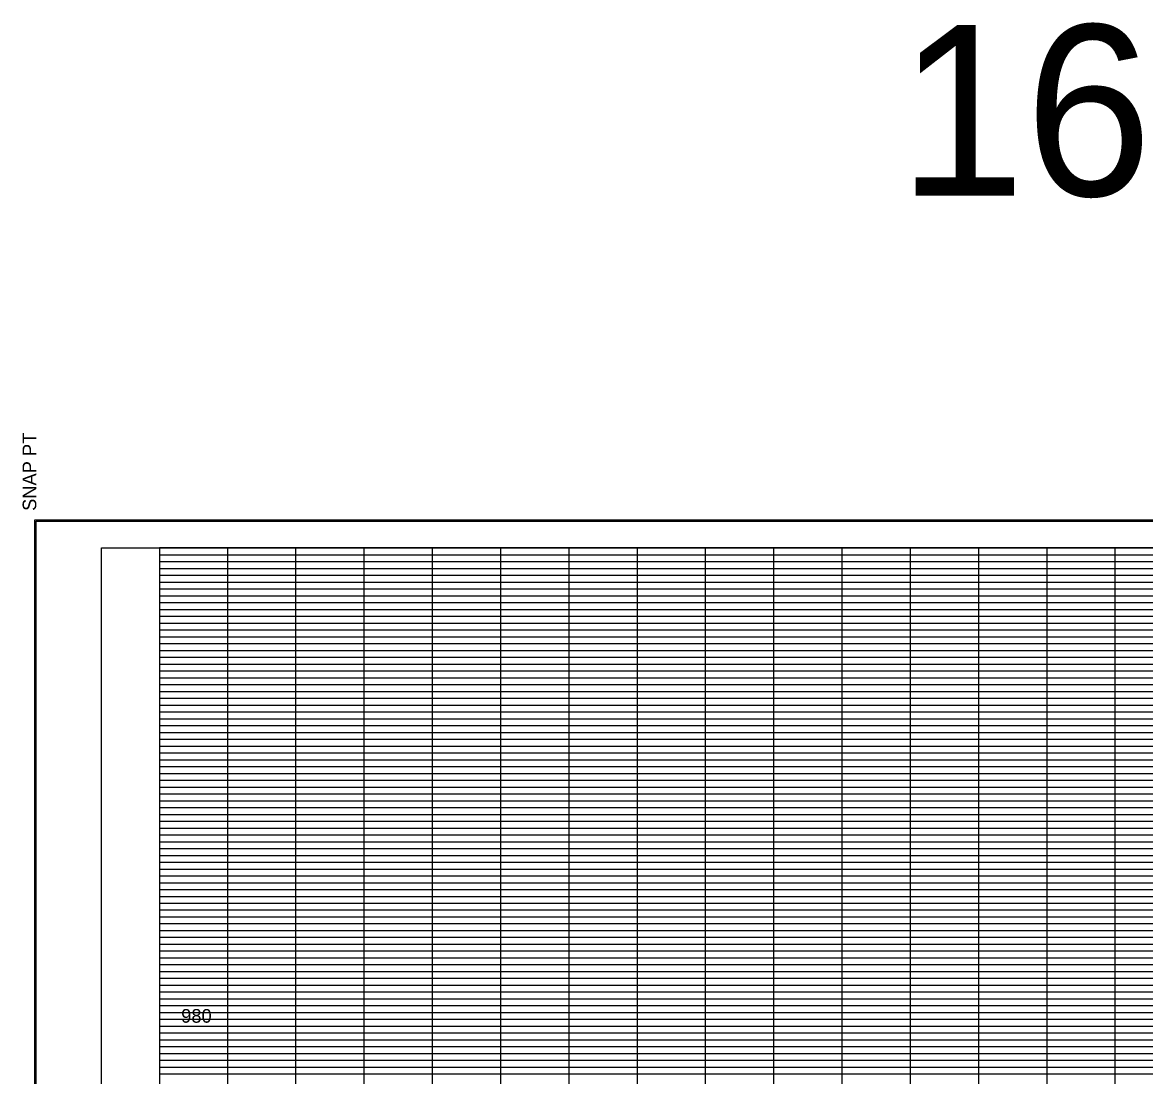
# Model space of a CAD drawing. Extents: x 2313580 to 2322968, y 282099 to 303247.
# Drawn here: x 2320006 to 2320334.7, y 287853.2 to 288161.5 of the extents above; entities that cross this region are included whole.
import ezdxf

# ---------------------------------------------------------------- set-up
doc = ezdxf.new("R2010")
doc.units = 0
for name, color, linetype in [('DESIGN - SCRATCH - User 1', 7, 'Continuous'), ('DESIGN - SHEET - Corner Text', 7, 'Continuous'), ('DESIGN - SHEET - Light Grid', 7, 'Continuous'), ('DESIGN - SHEET - Linework', 7, 'Continuous'), ('DESIGN - SHEET - Plot Shape', 7, 'Continuous'), ('DESIGN - TYPICAL - Text', 7, 'Continuous')]:
    doc.layers.add(name, color=color, linetype=linetype)

msp = doc.modelspace()

# ---------------------------------------------------------------- linework, layer by layer
at = {"layer": 'DESIGN - SHEET - Light Grid'}
for p, q in [((2320046.08, 288005.67), (2320206.08, 288005.67)), ((2320046.08, 288003.67), (2320206.08, 288003.67)), ((2320206.08, 288005.67), (2320366.08, 288005.67)), ((2320206.08, 288003.67), (2320366.08, 288003.67)), ((2320046.08, 288001.67), (2320206.08, 288001.67)), ((2320206.08, 288001.67), (2320366.08, 288001.67)), ((2320046.08, 287999.67), (2320206.08, 287999.67)), ((2320046.08, 287997.67), (2320206.08, 287997.67)), ((2320206.08, 287999.67), (2320366.08, 287999.67)), ((2320206.08, 287997.67), (2320366.08, 287997.67)), ((2320046.08, 287995.67), (2320206.08, 287995.67)), ((2320046.08, 287993.67), (2320206.08, 287993.67)), ((2320206.08, 287995.67), (2320366.08, 287995.67)), ((2320206.08, 287993.67), (2320366.08, 287993.67)), ((2320046.08, 287991.67), (2320206.08, 287991.67)), ((2320206.08, 287991.67), (2320366.08, 287991.67)), ((2320046.08, 287989.67), (2320206.08, 287989.67)), ((2320206.08, 287989.67), (2320366.08, 287989.67)), ((2320046.08, 287985.67), (2320206.08, 287985.67)), ((2320046.08, 287983.67), (2320206.08, 287983.67)), ((2320206.08, 287985.67), (2320366.08, 287985.67)), ((2320206.08, 287983.67), (2320366.08, 287983.67)), ((2320046.08, 287981.67), (2320206.08, 287981.67)), ((2320206.08, 287981.67), (2320366.08, 287981.67)), ((2320046.08, 287979.67), (2320206.08, 287979.67)), ((2320046.08, 287977.67), (2320206.08, 287977.67)), ((2320206.08, 287979.67), (2320366.08, 287979.67)), ((2320206.08, 287977.67), (2320366.08, 287977.67)), ((2320046.08, 287975.67), (2320206.08, 287975.67)), ((2320046.08, 287973.67), (2320206.08, 287973.67)), ((2320206.08, 287975.67), (2320366.08, 287975.67)), ((2320206.08, 287973.67), (2320366.08, 287973.67)), ((2320046.08, 287971.67), (2320206.08, 287971.67)), ((2320206.08, 287971.67), (2320366.08, 287971.67)), ((2320046.08, 287969.67), (2320206.08, 287969.67)), ((2320206.08, 287969.67), (2320366.08, 287969.67)), ((2320046.08, 287965.67), (2320206.08, 287965.67)), ((2320046.08, 287963.67), (2320206.08, 287963.67)), ((2320206.08, 287965.67), (2320366.08, 287965.67)), ((2320206.08, 287963.67), (2320366.08, 287963.67)), ((2320046.08, 287961.67), (2320206.08, 287961.67)), ((2320206.08, 287961.67), (2320366.08, 287961.67)), ((2320046.08, 287959.67), (2320206.08, 287959.67)), ((2320046.08, 287957.67), (2320206.08, 287957.67)), ((2320206.08, 287959.67), (2320366.08, 287959.67)), ((2320206.08, 287957.67), (2320366.08, 287957.67)), ((2320046.08, 287955.67), (2320206.08, 287955.67)), ((2320206.08, 287955.67), (2320366.08, 287955.67)), ((2320046.08, 287953.67), (2320206.08, 287953.67)), ((2320046.08, 287951.67), (2320206.08, 287951.67)), ((2320206.08, 287953.67), (2320366.08, 287953.67)), ((2320206.08, 287951.67), (2320366.08, 287951.67)), ((2320046.08, 287949.67), (2320206.08, 287949.67)), ((2320206.08, 287949.67), (2320366.08, 287949.67)), ((2320046.08, 287945.67), (2320206.08, 287945.67)), ((2320206.08, 287945.67), (2320366.08, 287945.67)), ((2320046.08, 287943.67), (2320206.08, 287943.67)), ((2320046.08, 287941.67), (2320206.08, 287941.67)), ((2320206.08, 287943.67), (2320366.08, 287943.67)), ((2320206.08, 287941.67), (2320366.08, 287941.67)), ((2320046.08, 287939.67), (2320206.08, 287939.67)), ((2320046.08, 287937.67), (2320206.08, 287937.67)), ((2320206.08, 287939.67), (2320366.08, 287939.67)), ((2320206.08, 287937.67), (2320366.08, 287937.67)), ((2320046.08, 287935.67), (2320206.08, 287935.67)), ((2320206.08, 287935.67), (2320366.08, 287935.67)), ((2320046.08, 287933.67), (2320206.08, 287933.67)), ((2320046.08, 287931.67), (2320206.08, 287931.67)), ((2320206.08, 287933.67), (2320366.08, 287933.67)), ((2320206.08, 287931.67), (2320366.08, 287931.67)), ((2320046.08, 287929.67), (2320206.08, 287929.67)), ((2320206.08, 287929.67), (2320366.08, 287929.67)), ((2320046.08, 287925.67), (2320206.08, 287925.67)), ((2320206.08, 287925.67), (2320366.08, 287925.67)), ((2320046.08, 287923.67), (2320206.08, 287923.67)), ((2320046.08, 287921.67), (2320206.08, 287921.67)), ((2320206.08, 287923.67), (2320366.08, 287923.67)), ((2320206.08, 287921.67), (2320366.08, 287921.67)), ((2320046.08, 287919.67), (2320206.08, 287919.67)), ((2320046.08, 287917.67), (2320206.08, 287917.67)), ((2320206.08, 287919.67), (2320366.08, 287919.67)), ((2320206.08, 287917.67), (2320366.08, 287917.67)), ((2320046.08, 287915.67), (2320206.08, 287915.67)), ((2320206.08, 287915.67), (2320366.08, 287915.67)), ((2320046.08, 287913.67), (2320206.08, 287913.67)), ((2320046.08, 287911.67), (2320206.08, 287911.67)), ((2320206.08, 287913.67), (2320366.08, 287913.67)), ((2320206.08, 287911.67), (2320366.08, 287911.67)), ((2320046.08, 287909.67), (2320206.08, 287909.67)), ((2320206.08, 287909.67), (2320366.08, 287909.67)), ((2320046.08, 287905.67), (2320206.08, 287905.67)), ((2320206.08, 287905.67), (2320366.08, 287905.67)), ((2320046.08, 287903.67), (2320206.08, 287903.67)), ((2320046.08, 287901.67), (2320206.08, 287901.67)), ((2320206.08, 287903.67), (2320366.08, 287903.67)), ((2320206.08, 287901.67), (2320366.08, 287901.67)), ((2320046.08, 287899.67), (2320206.08, 287899.67)), ((2320206.08, 287899.67), (2320366.08, 287899.67)), ((2320046.08, 287897.67), (2320206.08, 287897.67)), ((2320046.08, 287895.67), (2320206.08, 287895.67)), ((2320206.08, 287897.67), (2320366.08, 287897.67)), ((2320206.08, 287895.67), (2320366.08, 287895.67)), ((2320046.08, 287893.67), (2320206.08, 287893.67)), ((2320046.08, 287891.67), (2320206.08, 287891.67)), ((2320206.08, 287893.67), (2320366.08, 287893.67)), ((2320206.08, 287891.67), (2320366.08, 287891.67)), ((2320046.08, 287889.67), (2320206.08, 287889.67)), ((2320206.08, 287889.67), (2320366.08, 287889.67)), ((2320046.08, 287885.67), (2320206.08, 287885.67)), ((2320206.08, 287885.67), (2320366.08, 287885.67)), ((2320046.08, 287883.67), (2320206.08, 287883.67)), ((2320046.08, 287881.67), (2320206.08, 287881.67)), ((2320206.08, 287883.67), (2320366.08, 287883.67)), ((2320206.08, 287881.67), (2320366.08, 287881.67)), ((2320046.08, 287879.67), (2320206.08, 287879.67)), ((2320206.08, 287879.67), (2320366.08, 287879.67)), ((2320046.08, 287877.67), (2320206.08, 287877.67)), ((2320046.08, 287875.67), (2320206.08, 287875.67)), ((2320206.08, 287877.67), (2320366.08, 287877.67)), ((2320206.08, 287875.67), (2320366.08, 287875.67)), ((2320046.08, 287873.67), (2320206.08, 287873.67)), ((2320046.08, 287871.67), (2320206.08, 287871.67)), ((2320206.08, 287873.67), (2320366.08, 287873.67)), ((2320206.08, 287871.67), (2320366.08, 287871.67)), ((2320046.08, 287869.67), (2320206.08, 287869.67)), ((2320206.08, 287869.67), (2320366.08, 287869.67)), ((2320046.08, 287865.67), (2320206.08, 287865.67)), ((2320206.08, 287865.67), (2320366.08, 287865.67)), ((2320046.08, 287863.67), (2320206.08, 287863.67)), ((2320206.08, 287863.67), (2320366.08, 287863.67)), ((2320046.08, 287861.67), (2320206.08, 287861.67)), ((2320046.08, 287859.67), (2320206.08, 287859.67)), ((2320206.08, 287861.67), (2320366.08, 287861.67)), ((2320206.08, 287859.67), (2320366.08, 287859.67)), ((2320046.08, 287857.67), (2320206.08, 287857.67)), ((2320046.08, 287855.67), (2320206.08, 287855.67)), ((2320206.08, 287857.67), (2320366.08, 287857.67)), ((2320206.08, 287855.67), (2320366.08, 287855.67)), ((2320046.08, 287853.67), (2320206.08, 287853.67)), ((2320206.08, 287853.67), (2320366.08, 287853.67))]:
    msp.add_line(p, q, dxfattribs=at)
at = {"layer": 'DESIGN - SHEET - Linework'}
for p, q in [((2320009.62, 287579.39), (2320009.62, 288015.95)), ((2320009.62, 288015.95), (2320690.42, 288015.95)), ((2320066.08, 287587.67), (2320066.08, 288007.67)), ((2320086.08, 287587.67), (2320086.08, 288007.67)), ((2320106.08, 287587.67), (2320106.08, 288007.67)), ((2320126.08, 287587.67), (2320126.08, 288007.67)), ((2320146.08, 287587.67), (2320146.08, 288007.67)), ((2320166.08, 287587.67), (2320166.08, 288007.67)), ((2320186.08, 287587.67), (2320186.08, 288007.67)), ((2320206.08, 287587.67), (2320206.08, 288007.67)), ((2320226.08, 287587.67), (2320226.08, 288007.67)), ((2320246.08, 287587.67), (2320246.08, 288007.67)), ((2320266.08, 287587.67), (2320266.08, 288007.67)), ((2320286.08, 287587.67), (2320286.08, 288007.67)), ((2320306.08, 287587.67), (2320306.08, 288007.67)), ((2320326.08, 287587.67), (2320326.08, 288007.67)), ((2320046.08, 287987.67), (2320606.08, 287987.67)), ((2320046.08, 287967.67), (2320686.08, 287967.67)), ((2320046.08, 287947.67), (2320686.08, 287947.67)), ((2320046.08, 287927.67), (2320686.08, 287927.67)), ((2320046.08, 287907.67), (2320686.08, 287907.67)), ((2320046.08, 287887.67), (2320686.08, 287887.67)), ((2320046.08, 287867.67), (2320686.08, 287867.67))]:
    msp.add_line(p, q, dxfattribs=at)
msp.add_lwpolyline([(2320046.08, 288007.67), (2320046.08, 287587.67), (2320686.08, 287587.67), (2320686.08, 288007.67), (2320046.08, 288007.67)], dxfattribs=at)
at = {"layer": 'DESIGN - SHEET - Plot Shape'}
for points in [[(2320010.02, 288015.55), (2320690.02, 288015.55), (2320690.02, 287579.79), (2320010.02, 287579.79)], [(2320029.08, 288007.67), (2320686.08, 288007.67), (2320686.08, 287582.67), (2320029.08, 287582.67)]]:
    msp.add_lwpolyline(points, close=True, dxfattribs=at)

# ---------------------------------------------------------------- texts
at = {"layer": 'DESIGN - SCRATCH - User 1'}
msp.add_text('16', height=50, dxfattribs=at).set_placement((2320262.48, 288110.78))
at = {"layer": 'DESIGN - SHEET - Corner Text'}
msp.add_text('  SNAP PT', height=4, rotation=90, dxfattribs=at).set_placement((2320010.02, 288015.55))
at = {"layer": 'DESIGN - TYPICAL - Text'}
msp.add_text('980', height=4, dxfattribs=at).set_placement((2320052.46, 287868.67))

doc.saveas('drawing.dxf')
